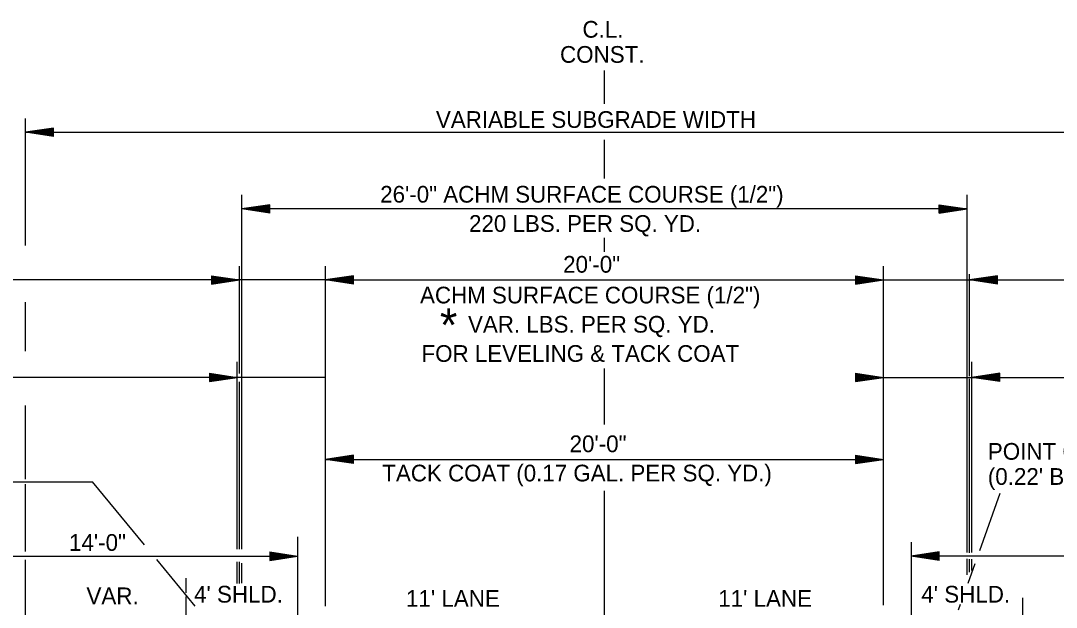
# Model space of a CAD drawing. Extents: x 2478 to 3210, y 439 to 841.
# Drawn here: x 2989.4 to 3063.6, y 795.5 to 837.5 of the extents above; entities that cross this region are included whole.
import ezdxf

# ---------------------------------------------------------------- set-up
doc = ezdxf.new("R2010")
doc.units = 0
for name, color, linetype in [('R_Annotation', 7, 'Continuous'), ('R_Centerline', 7, 'Continuous'), ('R_Dimension', 7, 'Continuous')]:
    doc.layers.add(name, color=color, linetype=linetype)

msp = doc.modelspace()

# ---------------------------------------------------------------- linework, layer by layer
at = {"layer": 'R_Centerline'}
for p, q in [((3031.233, 831.561), (3031.233, 833.958)), ((3031.233, 826.203), (3031.233, 828.982)), ((3031.234, 820.961), (3031.234, 821.958)), ((3031.233, 808.573), (3031.233, 812.586)), ((3031.233, 797.33), (3031.233, 803.809)), ((3031.233, 787.263), (3031.233, 797.33))]:
    msp.add_line(p, q, dxfattribs=at)
at = {"layer": 'R_Dimension'}
for p, q in [((2989.723, 821.417), (2989.723, 830.525)), ((2991.723, 829.825), (2989.723, 829.525)), ((2989.723, 829.525), (3070.657, 829.525)), ((2991.723, 829.225), (2989.723, 829.525)), ((2991.723, 829.775), (2990.057, 829.525)), ((2991.723, 829.275), (2990.057, 829.525)), ((2991.723, 829.724), (2990.401, 829.525)), ((2991.723, 829.326), (2990.401, 829.525)), ((2991.723, 829.674), (2990.734, 829.525)), ((2991.723, 829.376), (2990.734, 829.525)), ((2991.723, 829.623), (2991.073, 829.525)), ((2991.723, 829.428), (2991.073, 829.525)), ((2991.723, 829.572), (2991.407, 829.525)), ((2991.723, 829.478), (2991.407, 829.525)), ((2991.723, 829.225), (2991.723, 829.825)), ((3005.23, 799.63), (3005.23, 825.032)), ((3057.237, 819.434), (3057.237, 825.032)), ((3007.229, 824.332), (3005.229, 824.032)), ((3007.229, 824.282), (3005.563, 824.032)), ((3007.229, 824.231), (3005.907, 824.032)), ((3007.229, 824.181), (3006.24, 824.032)), ((3007.229, 823.732), (3007.229, 824.332)), ((3055.236, 824.332), (3057.236, 824.032)), ((3055.236, 823.732), (3055.236, 824.332)), ((3055.236, 824.282), (3056.902, 824.032)), ((3055.236, 824.231), (3056.558, 824.032)), ((3055.236, 824.181), (3056.225, 824.032)), ((3007.229, 823.732), (3005.229, 824.032)), ((3057.236, 824.032), (3005.229, 824.032)), ((3007.229, 823.782), (3005.563, 824.032)), ((3007.229, 823.833), (3005.907, 824.032)), ((3007.229, 823.883), (3006.24, 824.032)), ((3007.229, 824.13), (3006.579, 824.032)), ((3007.229, 823.935), (3006.579, 824.032)), ((3007.229, 824.079), (3006.913, 824.032)), ((3007.229, 823.985), (3006.913, 824.032)), ((3055.236, 824.13), (3055.886, 824.032)), ((3055.236, 824.079), (3055.552, 824.032)), ((3055.236, 823.732), (3057.236, 824.032)), ((3055.236, 823.935), (3055.886, 824.032)), ((3055.236, 823.833), (3056.558, 824.032)), ((3055.236, 823.782), (3056.902, 824.032)), ((3055.236, 823.883), (3056.225, 824.032)), ((3055.236, 823.985), (3055.552, 824.032)), ((3005.068, 812.217), (3005.068, 819.934)), ((3011.233, 795.549), (3011.233, 819.934)), ((3051.233, 795.606), (3051.233, 819.934)), ((3003.068, 819.234), (3005.068, 818.934)), ((3003.068, 819.234), (3003.068, 818.634)), ((3003.068, 819.184), (3004.734, 818.934)), ((3003.068, 819.133), (3004.39, 818.934)), ((3003.068, 819.083), (3004.057, 818.934)), ((3003.068, 819.031), (3003.718, 818.934)), ((3003.068, 818.981), (3003.384, 818.934)), ((3013.233, 819.234), (3011.233, 818.934)), ((3013.233, 819.184), (3011.567, 818.934)), ((3013.233, 819.133), (3011.911, 818.934)), ((3013.233, 819.083), (3012.244, 818.934)), ((3013.233, 819.032), (3012.583, 818.934)), ((3013.233, 818.981), (3012.917, 818.934)), ((3013.233, 818.634), (3013.233, 819.234)), ((3049.233, 819.234), (3051.233, 818.934)), ((3049.233, 819.234), (3049.233, 818.634)), ((3049.233, 819.184), (3050.899, 818.934)), ((3049.233, 819.133), (3050.555, 818.934)), ((3049.233, 819.083), (3050.222, 818.934)), ((3049.233, 819.031), (3049.883, 818.934)), ((3049.233, 818.981), (3049.549, 818.934)), ((3057.237, 799.383), (3057.237, 819.434)), ((3057.402, 812.031), (3057.402, 819.349)), ((3059.402, 819.234), (3057.402, 818.934)), ((3059.402, 819.184), (3057.736, 818.934)), ((3059.402, 819.133), (3058.08, 818.934)), ((3059.402, 819.083), (3058.413, 818.934)), ((3059.402, 819.032), (3058.752, 818.934)), ((3059.402, 818.981), (3059.086, 818.934)), ((3059.402, 818.634), (3059.402, 819.234)), ((3011.233, 818.934), (2959.991, 818.934)), ((3003.068, 818.634), (3005.068, 818.934)), ((3003.068, 818.836), (3003.718, 818.934)), ((3003.068, 818.735), (3004.39, 818.934)), ((3003.068, 818.684), (3004.734, 818.934)), ((3003.068, 818.785), (3004.057, 818.934)), ((3003.068, 818.887), (3003.384, 818.934)), ((3013.233, 818.634), (3011.233, 818.934)), ((3011.233, 818.934), (3051.233, 818.934)), ((3013.233, 818.684), (3011.567, 818.934)), ((3013.233, 818.735), (3011.911, 818.934)), ((3013.233, 818.785), (3012.244, 818.934)), ((3013.233, 818.837), (3012.583, 818.934)), ((3013.233, 818.887), (3012.917, 818.934)), ((3049.233, 818.634), (3051.233, 818.934)), ((3049.233, 818.836), (3049.883, 818.934)), ((3049.233, 818.735), (3050.555, 818.934)), ((3049.233, 818.684), (3050.899, 818.934)), ((3049.233, 818.785), (3050.222, 818.934)), ((3049.233, 818.887), (3049.549, 818.934)), ((3051.233, 818.934), (3105.077, 818.934)), ((3059.402, 818.634), (3057.402, 818.934)), ((3059.402, 818.684), (3057.736, 818.934)), ((3059.402, 818.735), (3058.08, 818.934)), ((3059.402, 818.785), (3058.413, 818.934)), ((3059.402, 818.837), (3058.752, 818.934)), ((3059.402, 818.887), (3059.086, 818.934)), ((2989.723, 813.822), (2989.723, 817.343)), ((3004.904, 799.63), (3004.904, 813.069)), ((3057.57, 799.383), (3057.57, 813.069)), ((3011.233, 811.949), (2959.991, 811.949)), ((3002.904, 812.249), (3004.904, 811.949)), ((3002.904, 812.249), (3002.904, 811.649)), ((3002.904, 812.199), (3004.57, 811.949)), ((3002.904, 812.148), (3004.226, 811.949)), ((3002.904, 812.098), (3003.893, 811.949)), ((3002.904, 812.046), (3003.554, 811.949)), ((3002.904, 811.996), (3003.22, 811.949)), ((3002.904, 811.649), (3004.904, 811.949)), ((3002.904, 811.851), (3003.554, 811.949)), ((3002.904, 811.75), (3004.226, 811.949)), ((3002.904, 811.699), (3004.57, 811.949)), ((3002.904, 811.8), (3003.893, 811.949)), ((3002.904, 811.902), (3003.22, 811.949)), ((3005.068, 799.63), (3005.068, 811.637)), ((3049.233, 812.249), (3051.233, 811.949)), ((3049.233, 812.249), (3049.233, 811.649)), ((3049.233, 812.199), (3050.899, 811.949)), ((3049.233, 812.148), (3050.555, 811.949)), ((3049.233, 812.098), (3050.222, 811.949)), ((3049.233, 812.046), (3049.883, 811.949)), ((3049.233, 811.996), (3049.549, 811.949)), ((3049.233, 811.649), (3051.233, 811.949)), ((3049.233, 811.851), (3049.883, 811.949)), ((3049.233, 811.75), (3050.555, 811.949)), ((3049.233, 811.699), (3050.899, 811.949)), ((3049.233, 811.8), (3050.222, 811.949)), ((3049.233, 811.902), (3049.549, 811.949)), ((3051.233, 811.949), (3105.077, 811.949)), ((3057.402, 799.38), (3057.402, 811.84)), ((3059.57, 812.249), (3057.57, 811.949)), ((3059.57, 811.649), (3057.57, 811.949)), ((3059.57, 812.199), (3057.904, 811.949)), ((3059.57, 811.699), (3057.904, 811.949)), ((3059.57, 812.148), (3058.248, 811.949)), ((3059.57, 811.75), (3058.248, 811.949)), ((3059.57, 812.098), (3058.581, 811.949)), ((3059.57, 811.8), (3058.581, 811.949)), ((3059.57, 812.047), (3058.92, 811.949)), ((3059.57, 811.852), (3058.92, 811.949)), ((3059.57, 811.996), (3059.254, 811.949)), ((3059.57, 811.902), (3059.254, 811.949)), ((3059.57, 811.649), (3059.57, 812.249)), ((2989.723, 804.648), (2989.723, 809.926)), ((3013.233, 806.368), (3011.233, 806.068)), ((3013.233, 805.768), (3013.233, 806.368)), ((3049.233, 806.368), (3051.233, 806.068)), ((3049.233, 806.368), (3049.233, 805.768)), ((3011.233, 806.068), (3051.233, 806.068)), ((3013.233, 805.768), (3011.233, 806.068)), ((3013.233, 806.318), (3011.567, 806.068)), ((3013.233, 805.818), (3011.567, 806.068)), ((3013.233, 806.267), (3011.911, 806.068)), ((3013.233, 805.869), (3011.911, 806.068)), ((3013.233, 806.217), (3012.244, 806.068)), ((3013.233, 805.919), (3012.244, 806.068)), ((3013.233, 806.166), (3012.583, 806.068)), ((3013.233, 805.971), (3012.583, 806.068)), ((3013.233, 806.115), (3012.917, 806.068)), ((3013.233, 806.021), (3012.917, 806.068)), ((3049.233, 806.318), (3050.899, 806.068)), ((3049.233, 806.267), (3050.555, 806.068)), ((3049.233, 806.217), (3050.222, 806.068)), ((3049.233, 806.165), (3049.883, 806.068)), ((3049.233, 806.115), (3049.549, 806.068)), ((3049.233, 805.768), (3051.233, 806.068)), ((3049.233, 805.97), (3049.883, 806.068)), ((3049.233, 805.869), (3050.555, 806.068)), ((3049.233, 805.818), (3050.899, 806.068)), ((3049.233, 805.919), (3050.222, 806.068)), ((3049.233, 806.021), (3049.549, 806.068)), ((2960.169, 804.453), (2994.516, 804.453)), ((2989.723, 799.461), (2989.723, 804.289)), ((2998.246, 799.954), (2994.516, 804.453)), ((3058.141, 799.536), (3059.611, 803.643)), ((3009.233, 800.517), (3009.233, 787.704)), ((3053.233, 800.13), (3053.233, 786.824)), ((2981.233, 799.13), (3009.233, 799.13)), ((3007.233, 799.43), (3009.233, 799.13)), ((3007.233, 799.43), (3007.233, 798.83)), ((3007.233, 799.38), (3008.899, 799.13)), ((3007.233, 799.329), (3008.555, 799.13)), ((3007.233, 799.279), (3008.222, 799.13)), ((3007.233, 799.227), (3007.883, 799.13)), ((3007.233, 799.177), (3007.549, 799.13)), ((3007.233, 798.83), (3009.233, 799.13)), ((3007.233, 799.032), (3007.883, 799.13)), ((3007.233, 798.931), (3008.555, 799.13)), ((3007.233, 798.88), (3008.899, 799.13)), ((3007.233, 798.981), (3008.222, 799.13)), ((3007.233, 799.083), (3007.549, 799.13)), ((3055.233, 799.43), (3053.233, 799.13)), ((3081.233, 799.13), (3053.233, 799.13)), ((3055.233, 798.83), (3053.233, 799.13)), ((3055.233, 799.38), (3053.567, 799.13)), ((3055.233, 798.88), (3053.567, 799.13)), ((3055.233, 799.329), (3053.911, 799.13)), ((3055.233, 798.931), (3053.911, 799.13)), ((3055.233, 799.279), (3054.244, 799.13)), ((3055.233, 798.981), (3054.244, 799.13)), ((3055.233, 799.228), (3054.583, 799.13)), ((3055.233, 799.033), (3054.583, 799.13)), ((3055.233, 799.177), (3054.917, 799.13)), ((3055.233, 799.083), (3054.917, 799.13)), ((3055.233, 798.83), (3055.233, 799.43)), ((2989.723, 785.001), (2989.723, 798.878)), ((3001.898, 795.55), (2999.131, 798.887)), ((3004.904, 797.179), (3004.904, 798.719)), ((3005.068, 797.179), (3005.068, 798.719)), ((3005.23, 797.2), (3005.23, 798.63)), ((3057.237, 797.801), (3057.237, 798.93)), ((3057.299, 797.182), (3057.805, 798.598)), ((3057.402, 797.988), (3057.402, 798.926)), ((3057.57, 798.102), (3057.57, 798.926)), ((3001.233, 796.503), (3001.233, 797.544)), ((3001.233, 792.885), (3001.233, 796.232)), ((3061.233, 792.631), (3061.233, 796.13)), ((3056.62, 795.286), (3056.761, 795.679))]:
    msp.add_line(p, q, dxfattribs=at)

# ---------------------------------------------------------------- texts
at = {"layer": 'R_Annotation'}
for s, height, p in [('C.L.', 1.2, (3029.656, 836.307)), ('CONST.', 1.2, (3028.045, 834.507)), ('VARIABLE SUBGRADE WIDTH', 1.197, (3019.15, 829.842)), ('26\'-0" ACHM SURFACE COURSE (1/2")', 1.197, (3015.153, 824.481)), ('220 LBS. PER SQ. YD.', 1.197, (3021.524, 822.386)), ('20\'-0"', 1.2, (3028.269, 819.457)), ('ACHM SURFACE COURSE (1/2")', 1.197, (3018.01, 817.253)), ('*', 2.4, (3019.435, 814.507)), ('VAR. LBS. PER SQ. YD. ', 1.197, (3021.45, 815.159)), ('FOR LEVELING & TACK COAT', 1.197, (3018.118, 813.064)), ('20\'-0"', 1.2, (3028.73, 806.587)), ('POINT OF SUPERELEVATION ROTATION ', 1.2, (3058.719, 806.043)), ('TACK COAT (0.17 GAL. PER SQ. YD.)', 1.197, (3015.305, 804.491)), ("(0.22' BELOW PROFILE GRADE).", 1.2, (3058.719, 804.243)), ('14\'-0"', 1.2, (2992.838, 799.512)), ('VAR.', 1.2, (2994.093, 795.683)), ("4' SHLD.", 1.2, (3001.806, 795.8)), ("4' SHLD.", 1.2, (3053.951, 795.8)), ("11' LANE", 1.2, (3017.004, 795.498)), ("11' LANE", 1.2, (3039.388, 795.498))]:
    msp.add_text(s, height=height, dxfattribs=at).set_placement(p)

doc.saveas('drawing.dxf')
